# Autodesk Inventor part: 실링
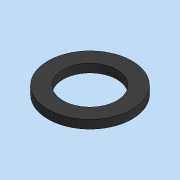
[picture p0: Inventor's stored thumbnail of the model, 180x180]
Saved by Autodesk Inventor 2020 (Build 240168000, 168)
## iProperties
Created: 2024-11
Part Number: 실링
Material: 고무
Document SubType Name: Modeling
Designer: 1강의실14
Density: 0.93 g/cm^3
Appearance: 기본값
Author: jhkim
Sending System: Autodesk Inventor 2025
Preprocessor: ST-DEVELOPER v20
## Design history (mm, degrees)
node "실링1"
node "솔리드2"
node "솔리드1"
